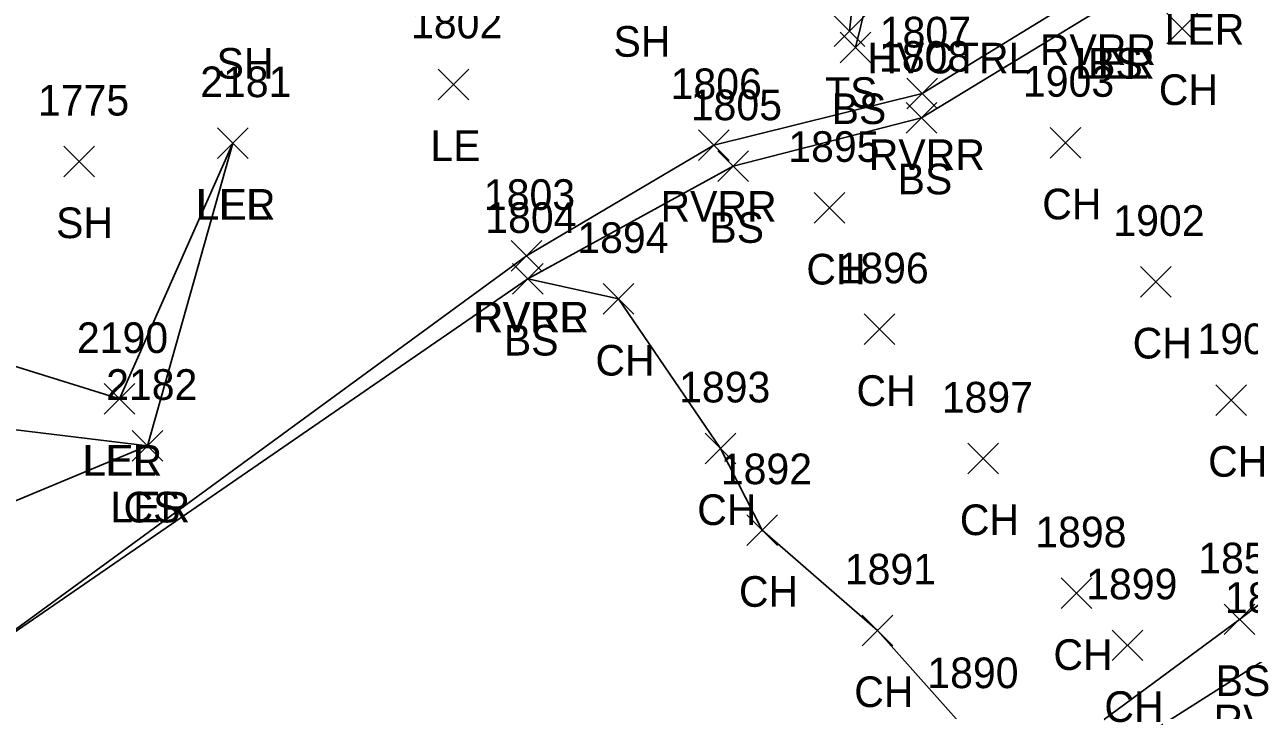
# Model space of a CAD drawing. Extents: x 1638344 to 1639591, y 610835 to 612202.
# Drawn here: x 1638606.9 to 1638686.8, y 611608.8 to 611653.6 of the extents above; entities that cross this region are included whole.
import ezdxf

# ---------------------------------------------------------------- set-up
doc = ezdxf.new("R2010")
doc.units = 0
for name, color, linetype in [('C_A', 7, 'Continuous'), ('L_A', 7, 'Continuous'), ('L_I', 7, 'Continuous'), ('L_TIC', 7, 'Continuous'), ('LARO', 7, 'Continuous'), ('LAWE', 7, 'Continuous'), ('LELB', 7, 'Continuous'), ('LSOGP', 7, 'Continuous')]:
    doc.layers.add(name, color=color, linetype=linetype)

msp = doc.modelspace()

# ---------------------------------------------------------------- linework, layer by layer
at = {"layer": 'L_TIC'}
for points in [[(1638659.747, 611652.111), (1638661.747, 611654.111)], [(1638661.747, 611652.111), (1638659.747, 611654.111)], [(1638681.441, 611652.301), (1638683.441, 611654.301)], [(1638683.441, 611652.301), (1638681.441, 611654.301)], [(1638660.143, 611651.058), (1638662.143, 611653.058)], [(1638662.143, 611651.058), (1638660.143, 611653.058)], [(1638633.919, 611648.646), (1638635.919, 611650.646)], [(1638635.919, 611648.646), (1638633.919, 611650.646)], [(1638664.496, 611648.056), (1638666.496, 611650.056)], [(1638666.496, 611648.056), (1638664.496, 611650.056)], [(1638664.449, 611646.47), (1638666.449, 611648.47)], [(1638666.449, 611646.47), (1638664.449, 611648.47)], [(1638619.521, 611644.813), (1638621.521, 611646.813)], [(1638621.521, 611644.813), (1638619.521, 611646.813)], [(1638619.521, 611644.813), (1638621.521, 611646.813)], [(1638621.521, 611644.813), (1638619.521, 611646.813)], [(1638650.909, 611644.684), (1638652.909, 611646.684)], [(1638652.909, 611644.684), (1638650.909, 611646.684)], [(1638673.837, 611644.839), (1638675.837, 611646.839)], [(1638675.837, 611644.839), (1638673.837, 611646.839)], [(1638609.502, 611643.613), (1638611.502, 611645.613)], [(1638611.502, 611643.613), (1638609.502, 611645.613)], [(1638652.167, 611643.307), (1638654.167, 611645.307)], [(1638654.167, 611643.307), (1638652.167, 611645.307)], [(1638658.449, 611640.588), (1638660.449, 611642.588)], [(1638660.449, 611640.588), (1638658.449, 611642.588)], [(1638638.67, 611637.455), (1638640.67, 611639.455)], [(1638640.67, 611637.455), (1638638.67, 611639.455)], [(1638638.67, 611637.455), (1638640.67, 611639.455)], [(1638640.67, 611637.455), (1638638.67, 611639.455)], [(1638638.761, 611635.952), (1638640.761, 611637.952)], [(1638640.761, 611635.952), (1638638.761, 611637.952)], [(1638679.735, 611635.759), (1638681.735, 611637.759)], [(1638681.735, 611635.759), (1638679.735, 611637.759)], [(1638644.687, 611634.643), (1638646.687, 611636.643)], [(1638646.687, 611634.643), (1638644.687, 611636.643)], [(1638661.717, 611632.663), (1638663.717, 611634.663)], [(1638663.717, 611632.663), (1638661.717, 611634.663)], [(1638612.13, 611628.116), (1638614.13, 611630.116)], [(1638614.13, 611628.116), (1638612.13, 611630.116)], [(1638612.13, 611628.116), (1638614.13, 611630.116)], [(1638614.13, 611628.116), (1638612.13, 611630.116)], [(1638684.657, 611628.041), (1638686.657, 611630.041)], [(1638686.657, 611628.041), (1638684.657, 611630.041)], [(1638613.95, 611625.059), (1638615.95, 611627.059)], [(1638615.95, 611625.059), (1638613.95, 611627.059)], [(1638613.95, 611625.059), (1638615.95, 611627.059)], [(1638615.95, 611625.059), (1638613.95, 611627.059)], [(1638651.328, 611624.89), (1638653.328, 611626.89)], [(1638653.328, 611624.89), (1638651.328, 611626.89)], [(1638668.46, 611624.232), (1638670.46, 611626.232)], [(1638670.46, 611624.232), (1638668.46, 611626.232)], [(1638654.049, 611619.554), (1638656.049, 611621.554)], [(1638656.049, 611619.554), (1638654.049, 611621.554)], [(1638674.562, 611615.434), (1638676.562, 611617.434)], [(1638676.562, 611615.434), (1638674.562, 611617.434)], [(1638685.193, 611613.735), (1638687.193, 611615.735)], [(1638687.193, 611613.735), (1638685.193, 611615.735)], [(1638661.571, 611613.009), (1638663.571, 611615.009)], [(1638663.571, 611613.009), (1638661.571, 611615.009)], [(1638677.891, 611612.039), (1638679.891, 611614.039)], [(1638679.891, 611612.039), (1638677.891, 611614.039)]]:
    msp.add_lwpolyline(points, dxfattribs=at)
at = {"layer": 'LARO'}
for points in [[(1638620.521, 611645.813), (1638614.95, 611626.059), (1638591.667, 611628.88), (1638596.282, 611634.378), (1638613.13, 611629.116)], [(1638620.521, 611645.813), (1638613.13, 611629.116)]]:
    msp.add_lwpolyline(points, dxfattribs=at)
at = {"layer": 'LAWE'}
for points in [[(1638639.67, 611638.455), (1638651.909, 611645.684), (1638665.496, 611649.056), (1638676.655, 611655.904), (1638679.763, 611666.345), (1638680.738, 611673.208), (1638671.065, 611682.751), (1638669.589, 611691.757), (1638672.343, 611706.91), (1638673.822, 611718.895), (1638672.065, 611725.227), (1638669.72, 611732.484), (1638668.237, 611746.392), (1638671.195, 611757.256), (1638673.317, 611772.941), (1638670.756, 611783.04), (1638669.117, 611796.001), (1638668.019, 611809.745), (1638668.561, 611829.322)], [(1638671.011, 611601.41), (1638687.934, 611612.159), (1638702.816, 611621.305), (1638722.828, 611637.898), (1638722.694, 611666.366), (1638723.119, 611679.868), (1638719.094, 611692.553), (1638717.187, 611697.341), (1638711.048, 611700.649), (1638718.685, 611716.114), (1638719.359, 611723.061), (1638714.323, 611734.571), (1638714.704, 611747.214), (1638712.56, 611755.84), (1638714.994, 611761.22), (1638711.865, 611767.72), (1638710.522, 611777.786), (1638714.936, 611789.326), (1638716.942, 611806.826), (1638715.698, 611824.36)], [(1638639.67, 611638.455), (1638603.159, 611611.77), (1638574.663, 611594.158), (1638565.405, 611585.152), (1638539.633, 611574.583)]]:
    msp.add_lwpolyline(points, dxfattribs=at)
at = {"layer": 'LELB'}
for points in [[(1638660.747, 611653.111), (1638661.619, 611661.306), (1638664.402, 611680.56)], [(1638666.378, 611670.719), (1638664.532, 611665.869), (1638661.143, 611652.058)], [(1638669.405, 611602.331), (1638686.193, 611614.735), (1638699.594, 611624.943), (1638720.779, 611638.494), (1638720.387, 611665.845)], [(1638639.761, 611636.952), (1638653.167, 611644.307), (1638665.449, 611647.47), (1638677.874, 611655.022)], [(1638614.95, 611626.059), (1638565.749, 611605.553)]]:
    msp.add_lwpolyline(points, dxfattribs=at)
at = {"layer": 'LSOGP'}
msp.add_lwpolyline([(1638574.663, 611594.158), (1638603.159, 611611.77), (1638639.761, 611636.952), (1638645.687, 611635.643), (1638652.328, 611625.89), (1638655.049, 611620.554), (1638662.571, 611614.009), (1638668.609, 611607.244)], dxfattribs=at)

# ---------------------------------------------------------------- texts
at = {"layer": 'C_A'}
msp.add_text('HVCTRL', height=2, dxfattribs=at).set_placement((1638661.919, 611650.363))
at = {"layer": 'L_A'}
for s, p in [('LER', (1638681.307, 611652.237)), ('SH', (1638645.353, 611651.45)), ('RVRR', (1638673.167, 611650.904)), ('SH', (1638619.46, 611650.019)), ('LER', (1638675.457, 611650.022)), ('LEL', (1638675.512, 611650.022)), ('BS', (1638676.315, 611650.022)), ('TS', (1638659.157, 611648.111)), ('CH', (1638680.929, 611648.301)), ('BS', (1638659.584, 611647.058)), ('LE', (1638633.407, 611644.646)), ('RVRR', (1638662.008, 611644.056)), ('BS', (1638663.89, 611642.47)), ('LER', (1638618.104, 611640.813)), ('LEL', (1638618.159, 611640.813)), ('RVRR', (1638648.421, 611640.684)), ('CH', (1638673.325, 611640.839)), ('SH', (1638608.99, 611639.613)), ('BS', (1638651.608, 611639.307)), ('CH', (1638657.937, 611636.588)), ('RVRR', (1638636.182, 611633.455)), ('RVRL', (1638636.237, 611633.455)), ('BS', (1638638.202, 611631.952)), ('CH', (1638679.223, 611631.759)), ('CH', (1638644.175, 611630.643)), ('CH', (1638661.205, 611628.663)), ('LER', (1638610.712, 611624.116)), ('LEL', (1638610.767, 611624.116)), ('CH', (1638684.145, 611624.041)), ('LER', (1638612.533, 611621.059)), ('CS', (1638613.391, 611621.059)), ('CH', (1638650.816, 611620.89)), ('CH', (1638667.948, 611620.232)), ('CH', (1638653.538, 611615.554)), ('CH', (1638674.05, 611611.434)), ('BS', (1638684.634, 611609.735)), ('CH', (1638661.059, 611609.009)), ('CH', (1638677.379, 611608.039)), ('RVRL', (1638684.501, 611607.159))]:
    msp.add_text(s, height=2, dxfattribs=at).set_placement(p)
at = {"layer": 'L_I'}
for s, p in [('1802', (1638632.147, 611652.646)), ('1807', (1638662.725, 611652.056)), ('1808', (1638662.677, 611650.47)), ('2181', (1638618.395, 611648.813)), ('2181', (1638618.395, 611648.813)), ('1806', (1638649.082, 611648.684)), ('1903', (1638672.066, 611648.839)), ('1775', (1638607.809, 611647.613)), ('1805', (1638650.396, 611647.307)), ('1895', (1638656.756, 611644.588)), ('1803', (1638636.898, 611641.455)), ('1803', (1638636.898, 611641.455)), ('1804', (1638636.989, 611639.952)), ('1902', (1638677.964, 611639.759)), ('1894', (1638642.994, 611638.643)), ('1896', (1638659.969, 611636.663)), ('2190', (1638610.35, 611632.116)), ('2190', (1638610.35, 611632.116)), ('1901', (1638683.452, 611632.041)), ('2182', (1638612.257, 611629.059)), ('2182', (1638612.257, 611629.059)), ('1893', (1638649.635, 611628.89)), ('1897', (1638666.767, 611628.232)), ('1892', (1638652.357, 611623.554)), ('1898', (1638672.869, 611619.434)), ('1853', (1638683.5, 611617.735)), ('1891', (1638660.445, 611617.009)), ('1899', (1638676.19, 611616.039)), ('1852', (1638685.241, 611615.159)), ('1890', (1638665.829, 611610.244))]:
    msp.add_text(s, height=2, dxfattribs=at).set_placement(p)

doc.saveas('drawing.dxf')
